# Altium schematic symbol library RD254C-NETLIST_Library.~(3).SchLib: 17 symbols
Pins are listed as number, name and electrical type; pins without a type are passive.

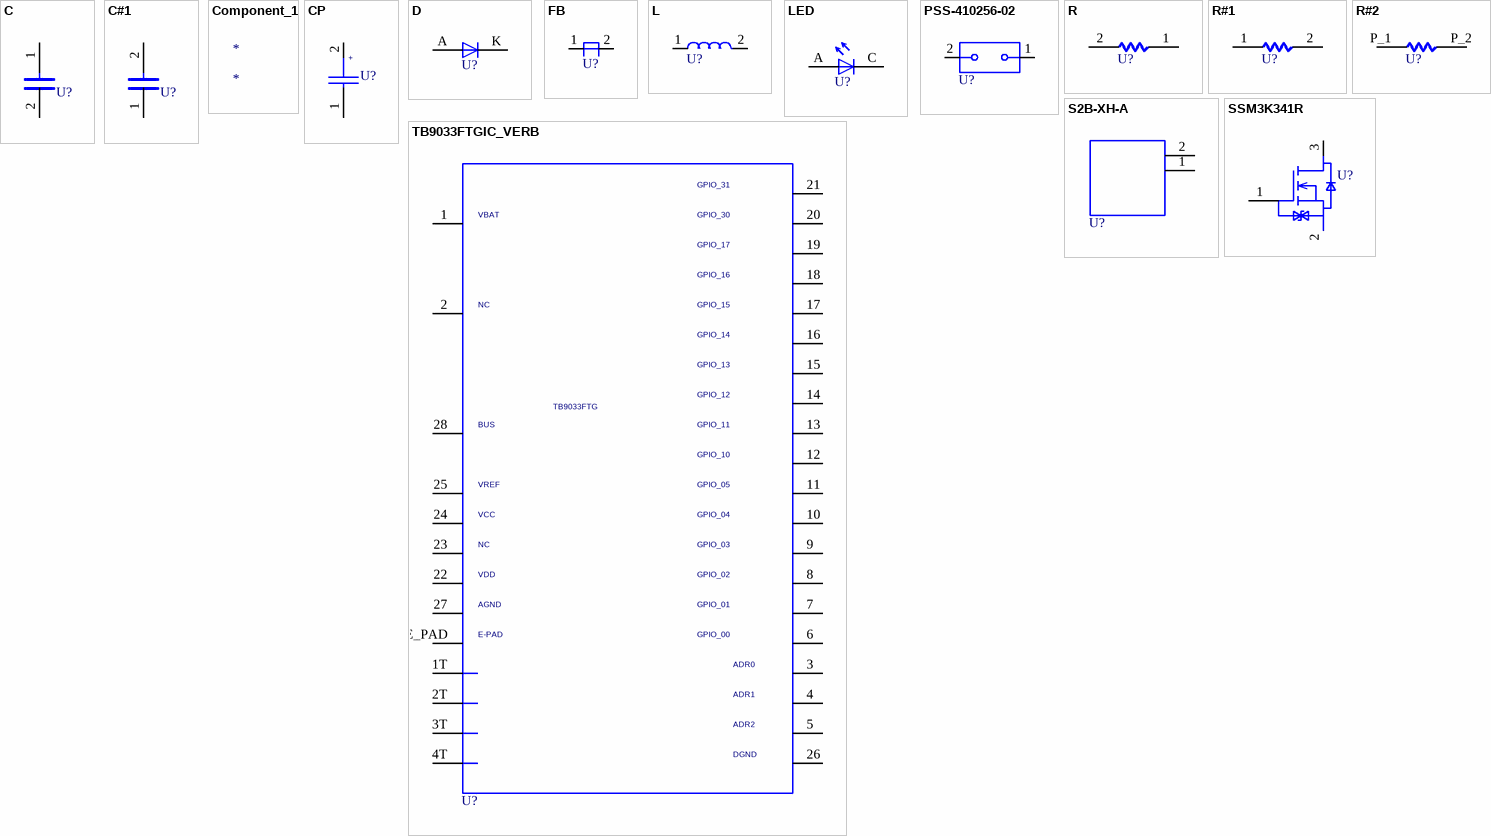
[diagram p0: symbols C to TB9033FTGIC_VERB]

## C
designator U?  (value not drawn)
OriginalSymbolOrigin: (2540,7620); Altium-Right: 20; Altium-Bottom: 10
pins: 1 2, 2 1

## C#1
designator U?, comment C  (value not drawn)
OriginalSymbolOrigin: (2540,7620); Altium-Right: 20; Altium-Bottom: 10
pins: 1, 2

## Component_1
designator *

## CP
designator U?  (value not drawn)
SAVEAREA0: -1450,-153,20294,13055; SAVECOUNT: 52; TIME: 15:02:55; UPDATEUSER: fukuda-y; UPDATETIME: 16:13:42; OriginalSymbolOrigin: (2540,10160); Altium-Right: 20
pins: 1, 2

## D
designator U?  (value not drawn)
SAVEAREA0: -225,-91,12804,7836; SAVECOUNT: 3; TIME: 14:49:55; UPDATEUSER: 19870035; UPDATETIME: 14:20:16; OriginalSymbolOrigin: (5080,5080); Altium-Right: 10; Altium-Bottom: 20
pins: A, K C

## FB
designator U?  (value not drawn)
SAVEAREA0: -63393,-16950,474261,314592; TIME: 14:30:25; UPDATEUSER: t5459927; UPDATETIME: 11:02:03; SAVECOUNT: 20; OriginalSymbolOrigin: (7620,7620); Altium-Right: 10
pins: 1, 2

## L
designator U?  (value not drawn)
OriginalSymbolOrigin: (2540,5080); Altium-Right: 30; Altium-Bottom: 20
pins: 1, 2

## LED
designator U?  (value not drawn)
SAVEAREA0: -6799,-183,19247,15664; TIME: 14:49:55; UPDATEUSER: fukuda-y; UPDATETIME: 13:54:07; SAVECOUNT: 4; OriginalSymbolOrigin: (5080,7620); Altium-Right: 10; Altium-Bottom: 30
pins: A, C

## PSS-410256-02
designator U?  (value not drawn)
SAVEAREA0: -63393,-16950,474261,314592; TIME: 14:30:25; UPDATEUSER: t5459927; UPDATETIME: 18:56:33; SAVECOUNT: 22; OriginalSymbolOrigin: (2540,5080); Altium-Right: 40; Altium-Bottom: 20
pins: 1 2, 2 1

## R
designator U?  (value not drawn)
OriginalSymbolOrigin: (5080,5080); Altium-Right: 20
pins: 1 2, 2 1

## R#1
designator U?, comment R  (value not drawn)
OriginalSymbolOrigin: (5080,5080); Altium-Right: 20
pins: 1, 2

## R#2
designator U?, comment R  (value not drawn)
OriginalSymbolOrigin: (5080,5080); Altium-Right: 20
pins: P_1 1, P_2 2

## S2B-XH-A
designator U?  (value not drawn)
SAVEAREA0: -63393,-16950,474261,314592; TIME: 14:30:25; UPDATEUSER: t5459927; UPDATETIME: 11:18:03; SAVECOUNT: 20; OriginalSymbolOrigin: (0,12700); Altium-Right: 50
pins: 1, 2

## SSM3K341R
designator U?  (value not drawn)
SAVEAREA0: -63393,-16950,474261,314592; TIME: 14:30:25; UPDATEUSER: t5459927; UPDATETIME: 12:01:19; SAVECOUNT: 22; OriginalSymbolOrigin: (5080,12700); Altium-Right: 40; Altium-Bottom: 50
pins: 1, 2, 3

## TB9033FTGIC_VERB
designator U?  VAL3: TB9033FTG  (hidden comment: TB9033FTGIC_VERB)
SAVEAREA0: -63393,-16950,474261,314592; TIME: 14:30:25; UPDATEUSER: t5459927; UPDATETIME: 17:47:26; SAVECOUNT: 27; OriginalSymbolOrigin: (5080,106680); Altium-Right: 220; Altium-Bottom: 420
pins: 1, 1T, 2, 2T, 3, 3T, 4, 4T, 5, 6, 7, 8, 9, 10, 11, 12, 13, 14, 15, 16, 17, 18, 19, 20, 21, 22, 23, 24, 25, 26, 27, 28, E_PAD

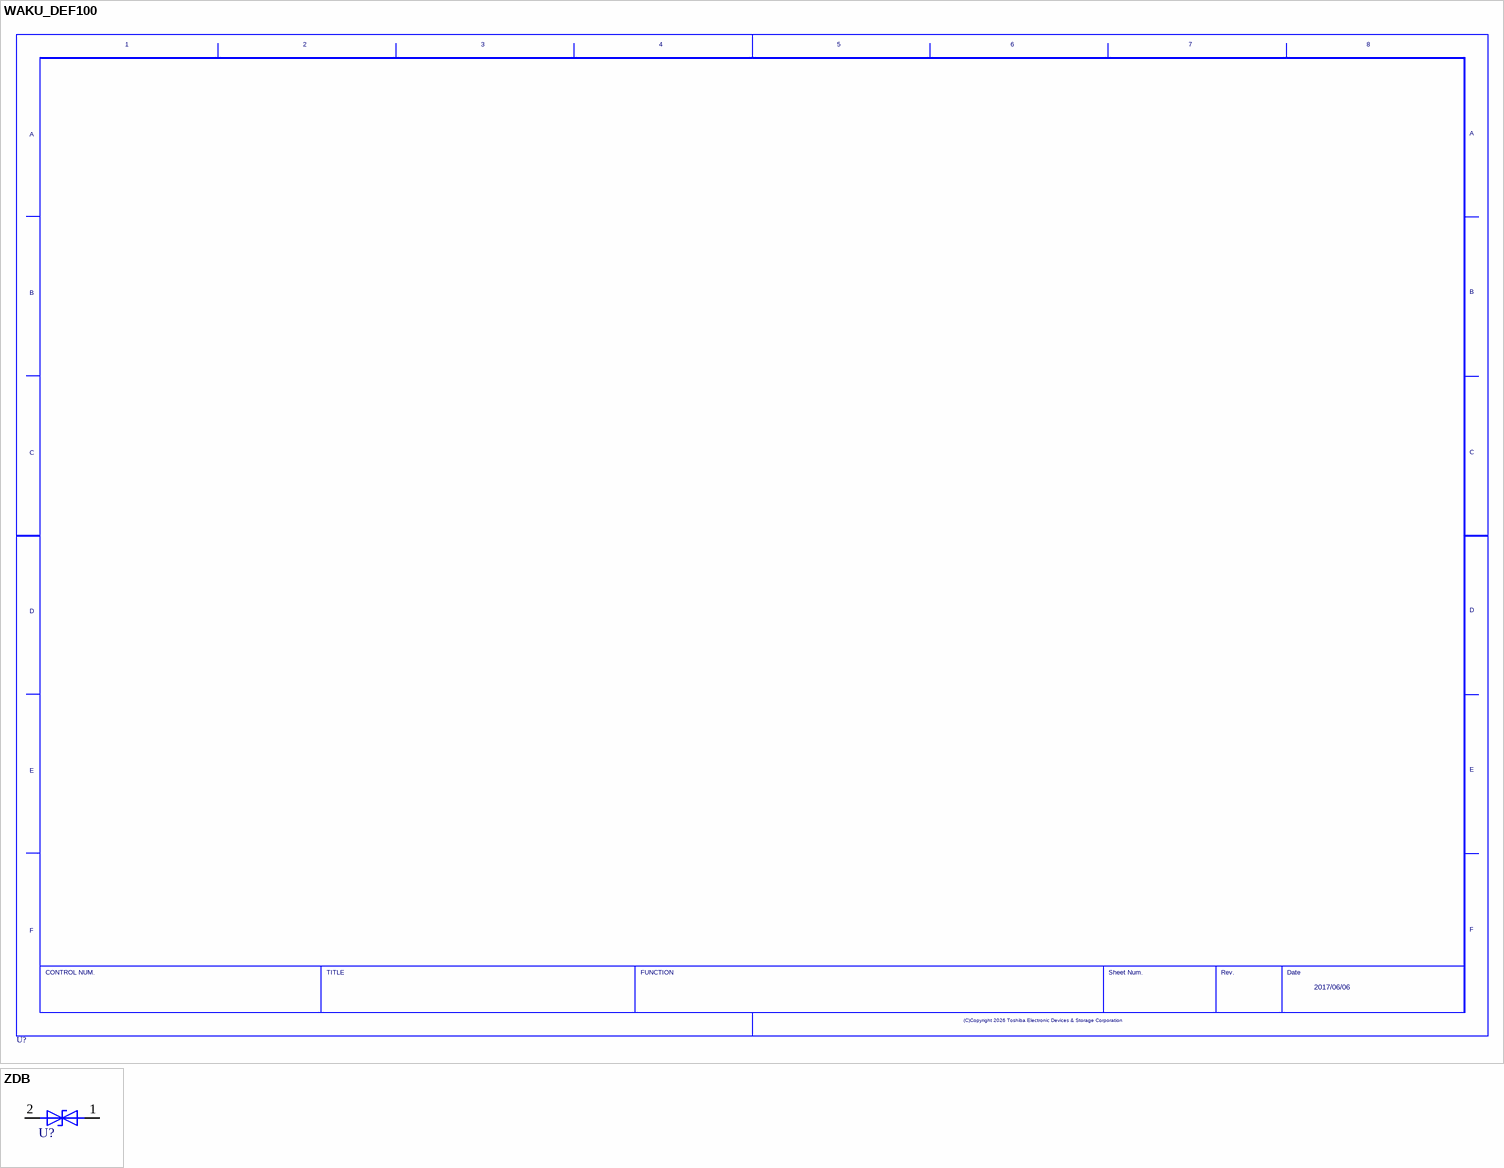
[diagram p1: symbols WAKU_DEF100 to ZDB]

## WAKU_DEF100
designator U?  DATE: 2017/06/06  (hidden comment: WAKU_DEF100)
PLOTTIME: HH:MM; SAVEAREA0: -63393,-16950,474261,314592; TIME: 14:30:25; UPDATEUSER: t5459927; UPDATETIME: 10:44:05; SAVECOUNT: 5; OriginalSymbolOrigin: (10160,284480); Altium-Right: 1570; Altium-Bottom: 1070

## ZDB
designator U?  (value not drawn)
SAVEAREA0: -4630,-153,17114,13055; TIME: 14:49:55; UPDATEUSER: fukuda-y; UPDATETIME: 08:22:19; SAVECOUNT: 6; OriginalSymbolOrigin: (2540,5080); Altium-Right: 30; Altium-Bottom: 20
pins: 1 2, 2 1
